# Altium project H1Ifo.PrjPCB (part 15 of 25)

## Sheet IfoSqz3A.SchDoc: D1800185
size C; Engineer: Daniel Sigg; DocumentNumber: 6; Revision: 4; SheetNumber: 6; SheetTotal: 10
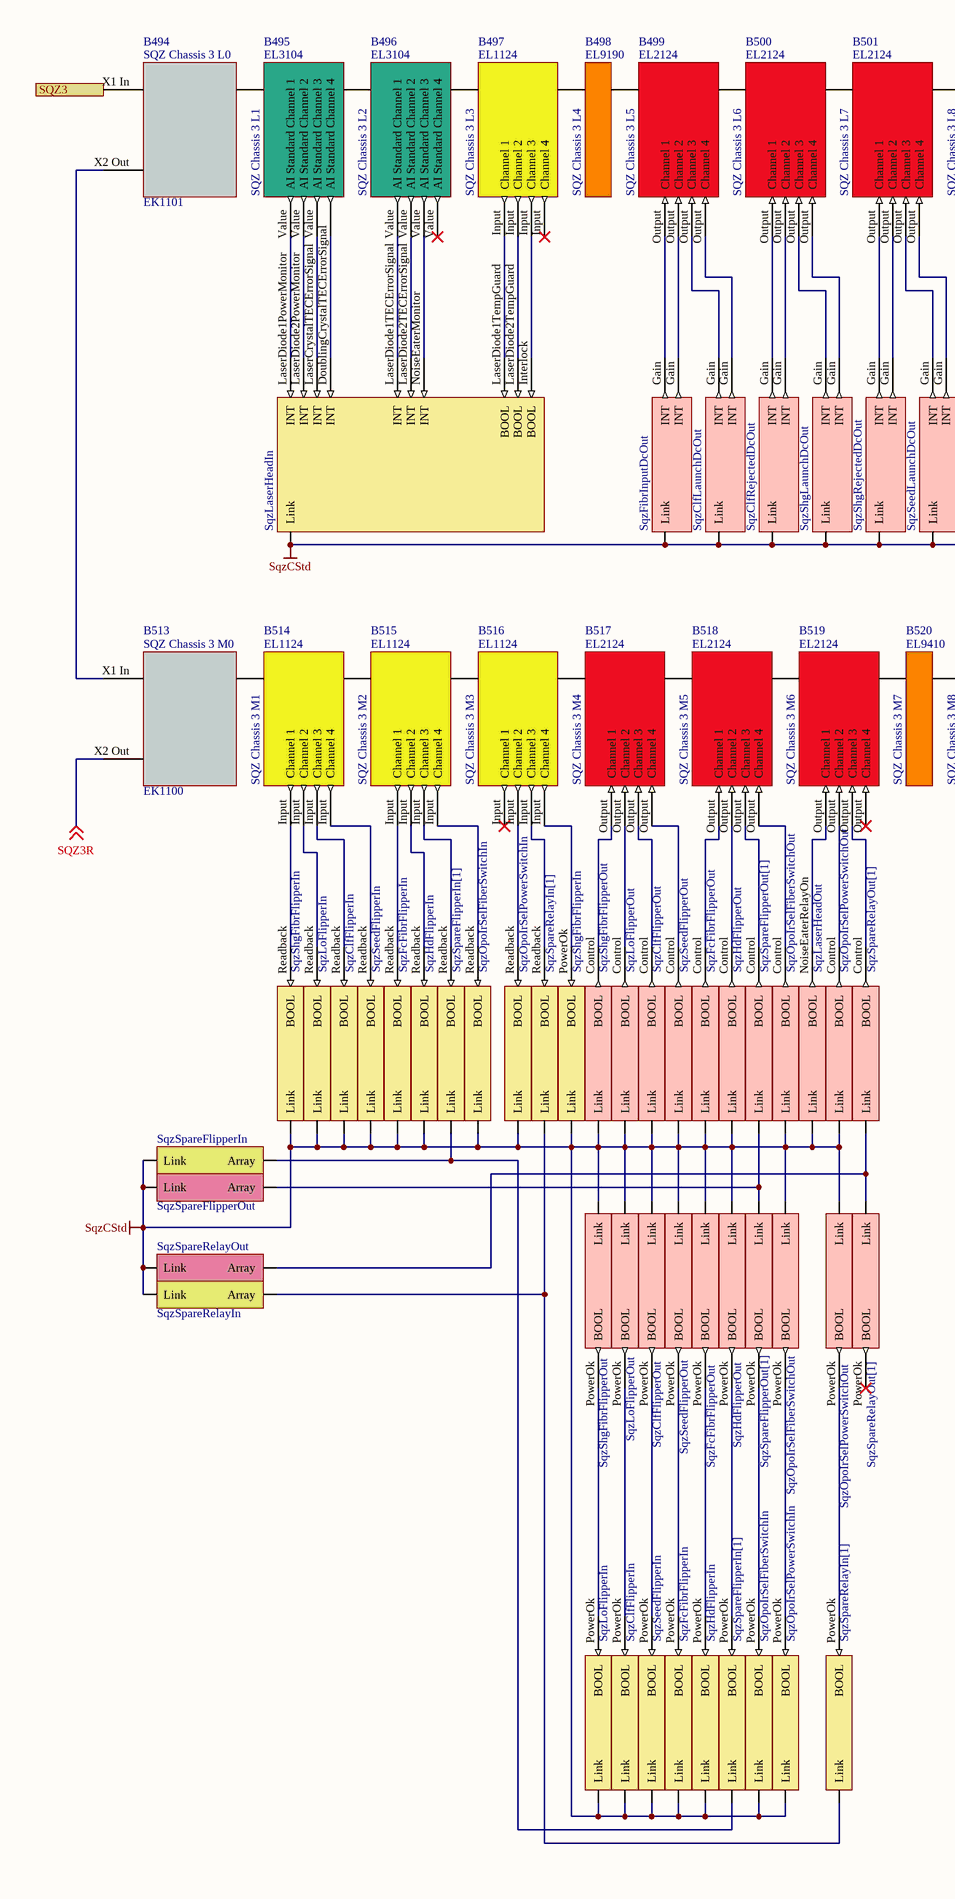
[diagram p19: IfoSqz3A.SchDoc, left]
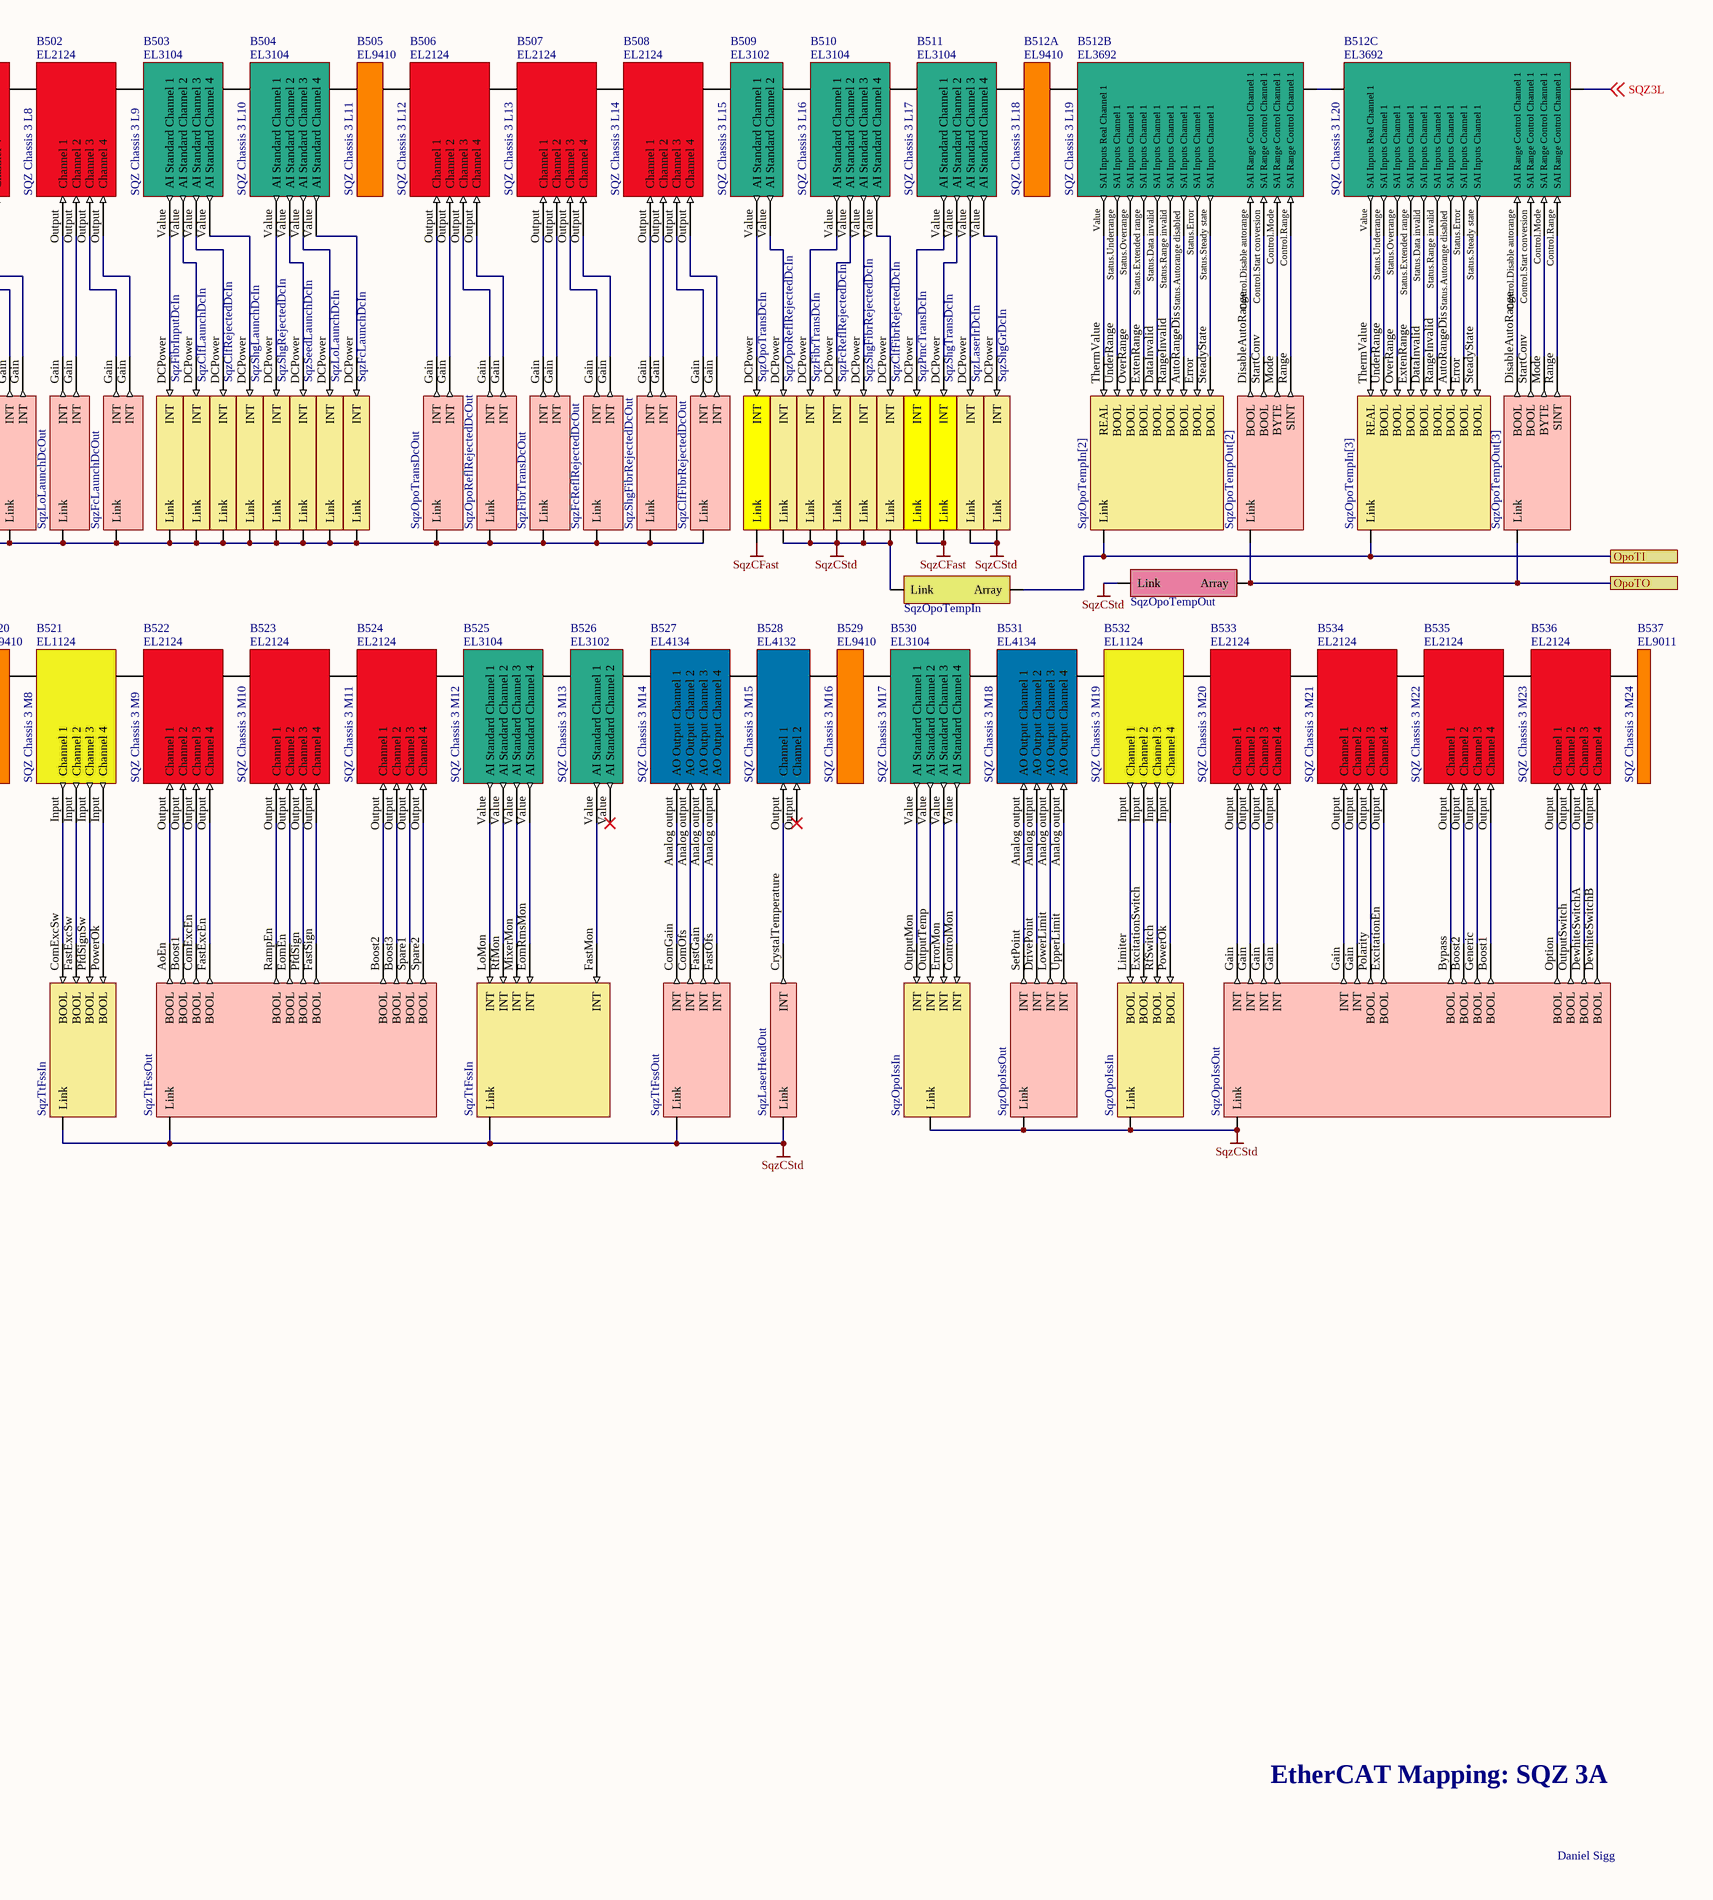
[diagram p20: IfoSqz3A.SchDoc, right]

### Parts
B494  SQZ Chassis 3 L0  Part Number: EK1101
B495  SQZ Chassis 3 L1  Part Number: EL3104  (mechanical)
B496  SQZ Chassis 3 L2  Part Number: EL3104  (mechanical)
B497  SQZ Chassis 3 L3  Part Number: EL1124  (mechanical)
B498  SQZ Chassis 3 L4  Part Number: EL9190  (mechanical)
B499  SQZ Chassis 3 L5  Part Number: EL2124  (mechanical)
B500  SQZ Chassis 3 L6  Part Number: EL2124  (mechanical)
B501  SQZ Chassis 3 L7  Part Number: EL2124  (mechanical)
B502  SQZ Chassis 3 L8  Part Number: EL2124  (mechanical)
B503  SQZ Chassis 3 L9  Part Number: EL3104  (mechanical)
B504  SQZ Chassis 3 L10  Part Number: EL3104  (mechanical)
B505  SQZ Chassis 3 L11  Part Number: EL9410  (mechanical)
B506  SQZ Chassis 3 L12  Part Number: EL2124  (mechanical)
B507  SQZ Chassis 3 L13  Part Number: EL2124  (mechanical)
B508  SQZ Chassis 3 L14  Part Number: EL2124  (mechanical)
B509  SQZ Chassis 3 L15  Part Number: EL3102  (mechanical)
B510  SQZ Chassis 3 L16  Part Number: EL3104  (mechanical)
B511  SQZ Chassis 3 L17  Part Number: EL3104  (mechanical)
B512A  SQZ Chassis 3 L18  Part Number: EL9410  (mechanical)
B512B  SQZ Chassis 3 L19  Part Number: EL3692  (mechanical)
B512C  SQZ Chassis 3 L20  Part Number: EL3692  (mechanical)
B513  SQZ Chassis 3 M0  Part Number: EK1100
B514  SQZ Chassis 3 M1  Part Number: EL1124  (mechanical)
B515  SQZ Chassis 3 M2  Part Number: EL1124  (mechanical)
B516  SQZ Chassis 3 M3  Part Number: EL1124  (mechanical)
B517  SQZ Chassis 3 M4  Part Number: EL2124  (mechanical)
B518  SQZ Chassis 3 M5  Part Number: EL2124  (mechanical)
B519  SQZ Chassis 3 M6  Part Number: EL2124  (mechanical)
B520  SQZ Chassis 3 M7  Part Number: EL9410  (mechanical)
B521  SQZ Chassis 3 M8  Part Number: EL1124  (mechanical)
B522  SQZ Chassis 3 M9  Part Number: EL2124  (mechanical)
B523  SQZ Chassis 3 M10  Part Number: EL2124  (mechanical)
B524  SQZ Chassis 3 M11  Part Number: EL2124  (mechanical)
B525  SQZ Chassis 3 M12  Part Number: EL3104  (mechanical)
B526  SQZ Chassis 3 M13  Part Number: EL3102  (mechanical)
B527  SQZ Chassis 3 M14  Part Number: EL4134  (mechanical)
B528  SQZ Chassis 3 M15  Part Number: EL4132  (mechanical)
B529  SQZ Chassis 3 M16  Part Number: EL9410  (mechanical)
B530  SQZ Chassis 3 M17  Part Number: EL3104  (mechanical)
B531  SQZ Chassis 3 M18  Part Number: EL4134  (mechanical)
B532  SQZ Chassis 3 M19  Part Number: EL1124  (mechanical)
B533  SQZ Chassis 3 M20  Part Number: EL2124  (mechanical)
B534  SQZ Chassis 3 M21  Part Number: EL2124  (mechanical)
B535  SQZ Chassis 3 M22  Part Number: EL2124  (mechanical)
B536  SQZ Chassis 3 M23  Part Number: EL2124  (mechanical)
B537  SQZ Chassis 3 M24  Part Number: EL9011  (mechanical)
V25  SqzOpoIssIn  (parts A,B of 2)  (no BOM)
V325  SqzLaserHeadOut  (parts A,B of 2)  (no BOM)
V356  SqzShgFibrFlipperIn  (parts A,B of 2)  (no BOM)
V357  SqzLoFlipperIn  (parts A,B of 2)  (no BOM)
V358  SqzClfFlipperIn  (parts A,B of 2)  (no BOM)
V359  SqzSeedFlipperIn  (parts A,B of 2)  (no BOM)
V360  SqzFcFibrFlipperIn  (parts A,B of 2)  (no BOM)
V361  SqzHdFlipperIn  (parts A,B of 2)  (no BOM)
V362  SqzSpareFlipperIn[1]  (parts A,B of 2)  (no BOM)
V363  SqzOpoIrSelFiberSwitchIn  (parts A,B of 2)  (no BOM)
V364  SqzOpoIrSelPowerSwitchIn  (parts A,B of 2)  (no BOM)
V365  SqzSpareRelayIn[1]  (parts A,B of 2)  (no BOM)
V366  SqzShgFibrFlipperOut  (parts A,B of 2)  (no BOM)
V367  SqzLoFlipperOut  (parts A,B of 2)  (no BOM)
V368  SqzClfFlipperOut  (parts A,B of 2)  (no BOM)
V369  SqzSeedFlipperOut  (parts A,B of 2)  (no BOM)
V370  SqzFcFibrFlipperOut  (parts A,B of 2)  (no BOM)
V371  SqzHdFlipperOut  (parts A,B of 2)  (no BOM)
V372  SqzSpareFlipperOut[1]  (parts A,B of 2)  (no BOM)
V373  SqzOpoIrSelFiberSwitchOut  (parts A,B of 2)  (no BOM)
V374  SqzOpoIrSelPowerSwitchOut  (parts A,B of 2)  (no BOM)
V375  SqzSpareRelayOut[1]  (parts A,B of 2)  (no BOM)
V380  SqzTtFssIn  (parts A,B of 2)  (no BOM)
V381  SqzTtFssOut  (parts A,B of 2)  (no BOM)
V437  SqzOpoIssOut  (parts A,B of 2)  (no BOM)
V459  SqzLaserHeadIn  (no BOM)
V460  SqzFibrInputDcOut  (no BOM)
V461  SqzClfLaunchDcOut  (no BOM)
V462  SqzClfRejectedDcOut  (no BOM)
V463  SqzShgLaunchDcOut  (no BOM)
V464  SqzShgRejectedDcOut  (no BOM)
V465  SqzSeedLaunchDcOut  (no BOM)
V466  SqzLoLaunchDcOut  (no BOM)
V467  SqzFcLaunchDcOut  (no BOM)
V468  SqzFibrInputDcIn  (no BOM)
V469  SqzClfLaunchDcIn  (no BOM)
V470  SqzClfRejectedDcIn  (no BOM)
V471  SqzShgLaunchDcIn  (no BOM)
V472  SqzShgRejectedDcIn  (no BOM)
V473  SqzSeedLaunchDcIn  (no BOM)
V474  SqzLoLaunchDcIn  (no BOM)
V475  SqzFcLaunchDcIn  (no BOM)
V476  SqzOpoTransDcOut  (no BOM)
V481  SqzOpoReflRejectedDcOut  (no BOM)
V482  SqzFibrTransDcOut  (no BOM)
V483  SqzFcReflRejectedDcOut  (no BOM)
V484  SqzShgFibrRejectedDcOut  (no BOM)
V485  SqzClfFibrRejectedDcOut  (no BOM)
V486  SqzOpoTransDcIn  (no BOM)
V487  SqzOpoReflRejectedDcIn  (no BOM)
V490  SqzFibrTransDcIn  (no BOM)
V491  SqzFcReflRejectedDcIn  (no BOM)
V492  SqzShgFibrRejectedDcIn  (no BOM)
V493  SqzClfFibrRejectedDcIn  (no BOM)
V495  SqzShgTransDcIn  (no BOM)
V496  SqzLaserIrDcIn  (no BOM)
V497  SqzShgGrDcIn  (no BOM)
V498  SqzOpoTempIn[2]  (no BOM)
V499  SqzOpoTempOut[2]  (no BOM)
V500  SqzOpoTempIn[3]  (no BOM)
V501  SqzOpoTempOut[3]  (no BOM)
V502  SqzOpoTempOut  (no BOM)
V503  SqzOpoTempIn  (no BOM)
V504  SqzSpareFlipperIn  (no BOM)
V505  SqzSpareFlipperOut  (no BOM)
V506  SqzSpareRelayOut  (no BOM)
V507  SqzSpareRelayIn  (no BOM)
V874  SqzPmcTransDcIn  (no BOM)

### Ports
OpoTI, OpoTO, SQZ3

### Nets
SqzCFast: V486.1(Link) V495.1(Link) V874.1(Link)
SqzCStd: V25.0(Link) V25.1(Link) V325.0(Link) V325.1(Link) V356.0(Link) V356.1(Link) V357.0(Link) V357.1(Link) V358.0(Link) V358.1(Link) V359.0(Link) V359.1(Link) V360.0(Link) V360.1(Link) V361.0(Link) V361.1(Link) V363.0(Link) V363.1(Link) V364.0(Link) V364.1(Link) V366.0(Link) V366.1(Link) V367.0(Link) V367.1(Link) V368.0(Link) V368.1(Link) V369.0(Link) V369.1(Link) V370.0(Link) V370.1(Link) V371.0(Link) V371.1(Link) V373.0(Link) V373.1(Link) V374.0(Link) V374.1(Link) V380.0(Link) V380.1(Link) V381.0(Link) V381.1(Link) V437.0(Link) V437.1(Link) V459.0(Link) V460.0(Link) V461.0(Link) V462.0(Link) V463.0(Link) V464.0(Link) V465.0(Link) V466.0(Link) V467.0(Link) V468.1(Link) V469.1(Link) V470.1(Link) V471.1(Link) V472.1(Link) V473.1(Link) V474.1(Link) V475.1(Link) V476.0(Link) V481.0(Link) V482.0(Link) V483.0(Link) V484.0(Link) V485.0(Link) V487.1(Link) V490.1(Link) V491.1(Link) V492.1(Link) V493.1(Link) V496.1(Link) V497.1(Link) V502.?1(Link) V503.?1(Link) V504.?1(Link) V505.?1(Link) V506.?1(Link) V507.?1(Link)
SQZ3L: B512C.Ebus(B) ; off-sheet SQZ3L
SQZ3R: B513.X2_Out(C) ; off-sheet SQZ3R
NetB473_X2 Out: B494.X1_In(A) ; port SQZ3
NetB494_Ebus: B494.Ebus(B) B495.Ebus(A)
NetB494_X2 Out: B494.X2_Out(C) B513.X1_In(A)
NetB495_Ebus: B495.Ebus(B) B496.Ebus(A)
NetB495_Value: B495.Value(AI_Standard_Channel_1) V459.LaserDiode1PowerMonitor(INT)
NetB495_Value: B495.Value(AI_Standard_Channel_2) V459.LaserDiode2PowerMonitor(INT)  [a separate net that carries the same name]
NetB495_Value: B495.Value(AI_Standard_Channel_3) V459.LaserCrystalTECErrorSignal(INT)  [a separate net that carries the same name]
NetB495_Value: B495.Value(AI_Standard_Channel_4) V459.DoublingCrystalTECErrorSignal(INT)  [a separate net that carries the same name]
NetB496_Ebus: B496.Ebus(B) B497.Ebus(A)
NetB496_Value: B496.Value(AI_Standard_Channel_1) V459.LaserDiode1TECErrorSignal(INT)
NetB496_Value: B496.Value(AI_Standard_Channel_2) V459.LaserDiode2TECErrorSignal(INT)  [a separate net that carries the same name]
NetB496_Value: B496.Value(AI_Standard_Channel_3) V459.NoiseEaterMonitor(INT)  [a separate net that carries the same name]
NetB497_Ebus: B497.Ebus(B) B498.Ebus(A)
NetB497_Input: B497.Input(Channel_1) V459.LaserDiode1TempGuard(BOOL)
NetB497_Input: B497.Input(Channel_2) V459.LaserDiode2TempGuard(BOOL)  [a separate net that carries the same name]
NetB497_Input: B497.Input(Channel_3) V459.Interlock(BOOL)  [a separate net that carries the same name]
NetB498_Ebus: B498.Ebus(B) B499.Ebus(A)
NetB499_Ebus: B499.Ebus(B) B500.Ebus(A)
NetB499_Output: B499.Output(Channel_1) V460.Gain(INT)
NetB499_Output: B499.Output(Channel_2) V460.Gain(INT)  [a separate net that carries the same name]
NetB499_Output: B499.Output(Channel_3) V461.Gain(INT)  [a separate net that carries the same name]
NetB499_Output: B499.Output(Channel_4) V461.Gain(INT)  [a separate net that carries the same name]
NetB500_Ebus: B500.Ebus(B) B501.Ebus(A)
NetB500_Output: B500.Output(Channel_1) V462.Gain(INT)
NetB500_Output: B500.Output(Channel_2) V462.Gain(INT)  [a separate net that carries the same name]
NetB500_Output: B500.Output(Channel_3) V463.Gain(INT)  [a separate net that carries the same name]
NetB500_Output: B500.Output(Channel_4) V463.Gain(INT)  [a separate net that carries the same name]
NetB501_Ebus: B501.Ebus(B) B502.Ebus(A)
NetB501_Output: B501.Output(Channel_1) V464.Gain(INT)
NetB501_Output: B501.Output(Channel_2) V464.Gain(INT)  [a separate net that carries the same name]
NetB501_Output: B501.Output(Channel_3) V465.Gain(INT)  [a separate net that carries the same name]
NetB501_Output: B501.Output(Channel_4) V465.Gain(INT)  [a separate net that carries the same name]
NetB502_Ebus: B502.Ebus(B) B503.Ebus(A)
NetB502_Output: B502.Output(Channel_1) V466.Gain(INT)
NetB502_Output: B502.Output(Channel_2) V466.Gain(INT)  [a separate net that carries the same name]
NetB502_Output: B502.Output(Channel_3) V467.Gain(INT)  [a separate net that carries the same name]
NetB502_Output: B502.Output(Channel_4) V467.Gain(INT)  [a separate net that carries the same name]
NetB503_Ebus: B503.Ebus(B) B504.Ebus(A)
NetB503_Value: B503.Value(AI_Standard_Channel_1) V468.DCPower(INT)
NetB503_Value: B503.Value(AI_Standard_Channel_2) V469.DCPower(INT)  [a separate net that carries the same name]
NetB503_Value: B503.Value(AI_Standard_Channel_3) V470.DCPower(INT)  [a separate net that carries the same name]
NetB503_Value: B503.Value(AI_Standard_Channel_4) V471.DCPower(INT)  [a separate net that carries the same name]
NetB504_Ebus: B504.Ebus(B) B505.Ebus(A)
NetB504_Value: B504.Value(AI_Standard_Channel_1) V472.DCPower(INT)
NetB504_Value: B504.Value(AI_Standard_Channel_2) V473.DCPower(INT)  [a separate net that carries the same name]
NetB504_Value: B504.Value(AI_Standard_Channel_3) V474.DCPower(INT)  [a separate net that carries the same name]
NetB504_Value: B504.Value(AI_Standard_Channel_4) V475.DCPower(INT)  [a separate net that carries the same name]
NetB505_Ebus: B505.Ebus(B) B506.Ebus(A)
NetB506_Ebus: B506.Ebus(B) B507.Ebus(A)
NetB506_Output: B506.Output(Channel_1) V476.Gain(INT)
NetB506_Output: B506.Output(Channel_2) V476.Gain(INT)  [a separate net that carries the same name]
NetB506_Output: B506.Output(Channel_3) V481.Gain(INT)  [a separate net that carries the same name]
NetB506_Output: B506.Output(Channel_4) V481.Gain(INT)  [a separate net that carries the same name]
NetB507_Ebus: B507.Ebus(B) B508.Ebus(A)
NetB507_Output: B507.Output(Channel_1) V482.Gain(INT)
NetB507_Output: B507.Output(Channel_2) V482.Gain(INT)  [a separate net that carries the same name]
NetB507_Output: B507.Output(Channel_3) V483.Gain(INT)  [a separate net that carries the same name]
NetB507_Output: B507.Output(Channel_4) V483.Gain(INT)  [a separate net that carries the same name]
NetB508_Ebus: B508.Ebus(B) B509.Ebus(A)
NetB508_Output: B508.Output(Channel_1) V484.Gain(INT)
NetB508_Output: B508.Output(Channel_2) V484.Gain(INT)  [a separate net that carries the same name]
NetB508_Output: B508.Output(Channel_3) V485.Gain(INT)  [a separate net that carries the same name]
NetB508_Output: B508.Output(Channel_4) V485.Gain(INT)  [a separate net that carries the same name]
NetB509_Ebus: B509.Ebus(B) B510.Ebus(A)
NetB509_Value: B509.Value(AI_Standard_Channel_1) V486.DCPower(INT)
NetB509_Value: B509.Value(AI_Standard_Channel_2) V487.DCPower(INT)  [a separate net that carries the same name]
NetB510_Ebus: B510.Ebus(B) B511.Ebus(A)
NetB510_Value: B510.Value(AI_Standard_Channel_1) V490.DCPower(INT)
NetB510_Value: B510.Value(AI_Standard_Channel_2) V491.DCPower(INT)  [a separate net that carries the same name]
NetB510_Value: B510.Value(AI_Standard_Channel_3) V492.DCPower(INT)  [a separate net that carries the same name]
NetB510_Value: B510.Value(AI_Standard_Channel_4) V493.DCPower(INT)  [a separate net that carries the same name]
NetB511_Ebus: B511.Ebus(B) B512A.Ebus(A)
NetB511_Value: B511.Value(AI_Standard_Channel_1) V874.DCPower(INT)
NetB511_Value: B511.Value(AI_Standard_Channel_2) V495.DCPower(INT)  [a separate net that carries the same name]
NetB511_Value: B511.Value(AI_Standard_Channel_3) V496.DCPower(INT)  [a separate net that carries the same name]
NetB511_Value: B511.Value(AI_Standard_Channel_4) V497.DCPower(INT)  [a separate net that carries the same name]
NetB512A_Ebus: B512A.Ebus(B) B512B.Ebus(A)
NetB512B_Control.Disable autorange: B512B.Control.Disable_autorange(SAI_Range_Control_Channel_1) V499.DisableAutoRange(BOOL)
NetB512B_Control.Mode: B512B.Control.Mode(SAI_Range_Control_Channel_1) V499.Mode(BYTE)
NetB512B_Control.Range: B512B.Control.Range(SAI_Range_Control_Channel_1) V499.Range(SINT)
NetB512B_Control.Start conversion: B512B.Control.Start_conversion(SAI_Range_Control_Channel_1) V499.StartConv(BOOL)
NetB512B_Ebus: B512B.Ebus(B) B512C.Ebus(A)
NetB512B_Status.Autorange disabled: B512B.Status.Autorange_disabled(SAI_Inputs_Channel_1) V498.AutoRangeDis(BOOL)
NetB512B_Status.Data invalid: B512B.Status.Data_invalid(SAI_Inputs_Channel_1) V498.DataInvalid(BOOL)
NetB512B_Status.Error: B512B.Status.Error(SAI_Inputs_Channel_1) V498.Error(BOOL)
NetB512B_Status.Extended range: B512B.Status.Extended_range(SAI_Inputs_Channel_1) V498.ExtenRange(BOOL)
NetB512B_Status.Overrange: B512B.Status.Overrange(SAI_Inputs_Channel_1) V498.OverRange(BOOL)
NetB512B_Status.Range invalid: B512B.Status.Range_invalid(SAI_Inputs_Channel_1) V498.RangeInvalid(BOOL)
NetB512B_Status.Steady state: B512B.Status.Steady_state(SAI_Inputs_Channel_1) V498.SteadyState(BOOL)
NetB512B_Status.Underrange: B512B.Status.Underrange(SAI_Inputs_Channel_1) V498.UnderRange(BOOL)
NetB512B_Value: B512B.Value(SAI_Inputs_Real_Channel_1) V498.ThermValue(REAL)
NetB512C_Control.Disable autorange: B512C.Control.Disable_autorange(SAI_Range_Control_Channel_1) V501.DisableAutoRange(BOOL)
NetB512C_Control.Mode: B512C.Control.Mode(SAI_Range_Control_Channel_1) V501.Mode(BYTE)
NetB512C_Control.Range: B512C.Control.Range(SAI_Range_Control_Channel_1) V501.Range(SINT)
NetB512C_Control.Start conversion: B512C.Control.Start_conversion(SAI_Range_Control_Channel_1) V501.StartConv(BOOL)
NetB512C_Status.Autorange disabled: B512C.Status.Autorange_disabled(SAI_Inputs_Channel_1) V500.AutoRangeDis(BOOL)
NetB512C_Status.Data invalid: B512C.Status.Data_invalid(SAI_Inputs_Channel_1) V500.DataInvalid(BOOL)
NetB512C_Status.Error: B512C.Status.Error(SAI_Inputs_Channel_1) V500.Error(BOOL)
NetB512C_Status.Extended range: B512C.Status.Extended_range(SAI_Inputs_Channel_1) V500.ExtenRange(BOOL)
NetB512C_Status.Overrange: B512C.Status.Overrange(SAI_Inputs_Channel_1) V500.OverRange(BOOL)
NetB512C_Status.Range invalid: B512C.Status.Range_invalid(SAI_Inputs_Channel_1) V500.RangeInvalid(BOOL)
NetB512C_Status.Steady state: B512C.Status.Steady_state(SAI_Inputs_Channel_1) V500.SteadyState(BOOL)
NetB512C_Status.Underrange: B512C.Status.Underrange(SAI_Inputs_Channel_1) V500.UnderRange(BOOL)
NetB512C_Value: B512C.Value(SAI_Inputs_Real_Channel_1) V500.ThermValue(REAL)
NetB513_Ebus: B513.Ebus(B) B514.Ebus(A)
NetB514_Ebus: B514.Ebus(B) B515.Ebus(A)
NetB514_Input: B514.Input(Channel_1) V356.Readback(BOOL)
NetB514_Input: B514.Input(Channel_2) V357.Readback(BOOL)  [a separate net that carries the same name]
NetB514_Input: B514.Input(Channel_3) V358.Readback(BOOL)  [a separate net that carries the same name]
NetB514_Input: B514.Input(Channel_4) V359.Readback(BOOL)  [a separate net that carries the same name]
NetB515_Ebus: B515.Ebus(B) B516.Ebus(A)
NetB515_Input: B515.Input(Channel_1) V360.Readback(BOOL)
NetB515_Input: B515.Input(Channel_2) V361.Readback(BOOL)  [a separate net that carries the same name]
NetB515_Input: B515.Input(Channel_3) V362.Readback(BOOL)  [a separate net that carries the same name]
NetB515_Input: B515.Input(Channel_4) V363.Readback(BOOL)  [a separate net that carries the same name]
NetB516_Ebus: B516.Ebus(B) B517.Ebus(A)
NetB516_Input: B516.Input(Channel_1) V364.Readback(BOOL)
NetB516_Input: B516.Input(Channel_3) V365.Readback(BOOL)  [a separate net that carries the same name]
NetB516_Input: B516.Input(Channel_4) V356.PowerOk(BOOL)  [a separate net that carries the same name]
NetB517_Ebus: B517.Ebus(B) B518.Ebus(A)
NetB517_Output: B517.Output(Channel_1) V366.Control(BOOL)
NetB517_Output: B517.Output(Channel_2) V367.Control(BOOL)  [a separate net that carries the same name]
NetB517_Output: B517.Output(Channel_3) V368.Control(BOOL)  [a separate net that carries the same name]
NetB517_Output: B517.Output(Channel_4) V369.Control(BOOL)  [a separate net that carries the same name]
NetB518_Ebus: B518.Ebus(B) B519.Ebus(A)
NetB518_Output: B518.Output(Channel_1) V370.Control(BOOL)
NetB518_Output: B518.Output(Channel_2) V371.Control(BOOL)  [a separate net that carries the same name]
NetB518_Output: B518.Output(Channel_3) V372.Control(BOOL)  [a separate net that carries the same name]
NetB518_Output: B518.Output(Channel_4) V373.Control(BOOL)  [a separate net that carries the same name]
NetB519_Ebus: B519.Ebus(B) B520.Ebus(A)
NetB519_Output: B519.Output(Channel_1) V325.NoiseEaterRelayOn(BOOL)
NetB519_Output: B519.Output(Channel_2) V374.Control(BOOL)  [a separate net that carries the same name]
NetB519_Output: B519.Output(Channel_3) V375.Control(BOOL)  [a separate net that carries the same name]
NetB520_Ebus: B520.Ebus(B) B521.Ebus(A)
NetB521_Ebus: B521.Ebus(B) B522.Ebus(A)
NetB521_Input: B521.Input(Channel_1) V380.ComExcSw(BOOL)
NetB521_Input: B521.Input(Channel_2) V380.FastExcSw(BOOL)  [a separate net that carries the same name]
NetB521_Input: B521.Input(Channel_3) V380.PfdSignSw(BOOL)  [a separate net that carries the same name]
NetB521_Input: B521.Input(Channel_4) V380.PowerOk(BOOL)  [a separate net that carries the same name]
NetB522_Ebus: B522.Ebus(B) B523.Ebus(A)
NetB522_Output: B522.Output(Channel_1) V381.AoEn(BOOL)
NetB522_Output: B522.Output(Channel_2) V381.Boost1(BOOL)  [a separate net that carries the same name]
NetB522_Output: B522.Output(Channel_3) V381.ComExcEn(BOOL)  [a separate net that carries the same name]
NetB522_Output: B522.Output(Channel_4) V381.FastExcEn(BOOL)  [a separate net that carries the same name]
NetB523_Ebus: B523.Ebus(B) B524.Ebus(A)
NetB523_Output: B523.Output(Channel_1) V381.RampEn(BOOL)
NetB523_Output: B523.Output(Channel_2) V381.EomEn(BOOL)  [a separate net that carries the same name]
NetB523_Output: B523.Output(Channel_3) V381.PfdSign(BOOL)  [a separate net that carries the same name]
NetB523_Output: B523.Output(Channel_4) V381.FastSign(BOOL)  [a separate net that carries the same name]
NetB524_Ebus: B524.Ebus(B) B525.Ebus(A)
NetB524_Output: B524.Output(Channel_1) V381.Boost2(BOOL)
NetB524_Output: B524.Output(Channel_2) V381.Boost3(BOOL)  [a separate net that carries the same name]
NetB524_Output: B524.Output(Channel_3) V381.Spare1(BOOL)  [a separate net that carries the same name]
NetB524_Output: B524.Output(Channel_4) V381.Spare2(BOOL)  [a separate net that carries the same name]
NetB525_Ebus: B525.Ebus(B) B526.Ebus(A)
NetB525_Value: B525.Value(AI_Standard_Channel_1) V380.LoMon(INT)
NetB525_Value: B525.Value(AI_Standard_Channel_2) V380.RfMon(INT)  [a separate net that carries the same name]
NetB525_Value: B525.Value(AI_Standard_Channel_3) V380.MixerMon(INT)  [a separate net that carries the same name]
NetB525_Value: B525.Value(AI_Standard_Channel_4) V380.EomRmsMon(INT)  [a separate net that carries the same name]
NetB526_Ebus: B526.Ebus(B) B527.Ebus(A)
NetB526_Value: B526.Value(AI_Standard_Channel_1) V380.FastMon(INT)
NetB527_Analog output: B527.Analog_output(AO_Output_Channel_1) V381.ComGain(INT)
NetB527_Analog output: B527.Analog_output(AO_Output_Channel_2) V381.ComOfs(INT)  [a separate net that carries the same name]
NetB527_Analog output: B527.Analog_output(AO_Output_Channel_3) V381.FastGain(INT)  [a separate net that carries the same name]
NetB527_Analog output: B527.Analog_output(AO_Output_Channel_4) V381.FastOfs(INT)  [a separate net that carries the same name]
NetB527_Ebus: B527.Ebus(B) B528.Ebus(A)
NetB528_Ebus: B528.Ebus(B) B529.Ebus(A)
NetB528_Output: B528.Output(Channel_1) V325.CrystalTemperature(INT)
NetB529_Ebus: B529.Ebus(B) B530.Ebus(A)
NetB530_Ebus: B530.Ebus(B) B531.Ebus(A)
NetB530_Value: B530.Value(AI_Standard_Channel_1) V25.OutputMon(INT)
NetB530_Value: B530.Value(AI_Standard_Channel_2) V25.OutputTemp(INT)  [a separate net that carries the same name]
NetB530_Value: B530.Value(AI_Standard_Channel_3) V25.ErrorMon(INT)  [a separate net that carries the same name]
NetB530_Value: B530.Value(AI_Standard_Channel_4) V25.ControlMon(INT)  [a separate net that carries the same name]
NetB531_Analog output: B531.Analog_output(AO_Output_Channel_1) V437.SetPoint(INT)
NetB531_Analog output: B531.Analog_output(AO_Output_Channel_2) V437.DrivePoint(INT)  [a separate net that carries the same name]
NetB531_Analog output: B531.Analog_output(AO_Output_Channel_3) V437.LowerLimit(INT)  [a separate net that carries the same name]
NetB531_Analog output: B531.Analog_output(AO_Output_Channel_4) V437.UpperLimit(INT)  [a separate net that carries the same name]
NetB531_Ebus: B531.Ebus(B) B532.Ebus(A)
NetB532_Ebus: B532.Ebus(B) B533.Ebus(A)
NetB532_Input: B532.Input(Channel_1) V25.Limiter(BOOL)
NetB532_Input: B532.Input(Channel_2) V25.ExcitationSwitch(BOOL)  [a separate net that carries the same name]
NetB532_Input: B532.Input(Channel_3) V25.RfSwitch(BOOL)  [a separate net that carries the same name]
NetB532_Input: B532.Input(Channel_4) V25.PowerOk(BOOL)  [a separate net that carries the same name]
NetB533_Ebus: B533.Ebus(B) B534.Ebus(A)
NetB533_Output: B533.Output(Channel_1) V437.Gain(INT)
NetB533_Output: B533.Output(Channel_2) V437.Gain(INT)  [a separate net that carries the same name]
NetB533_Output: B533.Output(Channel_3) V437.Gain(INT)  [a separate net that carries the same name]
NetB533_Output: B533.Output(Channel_4) V437.Gain(INT)  [a separate net that carries the same name]
NetB534_Ebus: B534.Ebus(B) B535.Ebus(A)
NetB534_Output: B534.Output(Channel_1) V437.Gain(INT)
NetB534_Output: B534.Output(Channel_2) V437.Gain(INT)  [a separate net that carries the same name]
NetB534_Output: B534.Output(Channel_3) V437.Polarity(BOOL)  [a separate net that carries the same name]
NetB534_Output: B534.Output(Channel_4) V437.ExcitationEn(BOOL)  [a separate net that carries the same name]
NetB535_Ebus: B535.Ebus(B) B536.Ebus(A)
NetB535_Output: B535.Output(Channel_1) V437.Bypass(BOOL)
NetB535_Output: B535.Output(Channel_2) V437.Boost2(BOOL)  [a separate net that carries the same name]
NetB535_Output: B535.Output(Channel_3) V437.Generic(BOOL)  [a separate net that carries the same name]
NetB535_Output: B535.Output(Channel_4) V437.Boost1(BOOL)  [a separate net that carries the same name]
NetB536_Ebus: B536.Ebus(B) B537.Ebus(A)
NetB536_Output: B536.Output(Channel_1) V437.Option(BOOL)
NetB536_Output: B536.Output(Channel_2) V437.OutputSwitch(BOOL)  [a separate net that carries the same name]
NetB536_Output: B536.Output(Channel_3) V437.DewhiteSwitchA(BOOL)  [a separate net that carries the same name]
NetB536_Output: B536.Output(Channel_4) V437.DewhiteSwitchB(BOOL)  [a separate net that carries the same name]
NetV357_PowerOk: V357.PowerOk(BOOL) V366.PowerOk(BOOL)
NetV358_PowerOk: V358.PowerOk(BOOL) V367.PowerOk(BOOL)
NetV359_PowerOk: V359.PowerOk(BOOL) V368.PowerOk(BOOL)
NetV360_PowerOk: V360.PowerOk(BOOL) V369.PowerOk(BOOL)
NetV361_PowerOk: V361.PowerOk(BOOL) V370.PowerOk(BOOL)
NetV362_0: V362.0(Link) V362.1(Link) V504.?2(Array)
NetV362_PowerOk: V362.PowerOk(BOOL) V371.PowerOk(BOOL)
NetV363_PowerOk: V363.PowerOk(BOOL) V372.PowerOk(BOOL)
NetV364_PowerOk: V364.PowerOk(BOOL) V373.PowerOk(BOOL)
NetV365_0: V365.0(Link) V365.1(Link) V507.?2(Array)
NetV365_PowerOk: V365.PowerOk(BOOL) V374.PowerOk(BOOL)
NetV372_0: V372.0(Link) V372.1(Link) V505.?2(Array)
NetV375_0: V375.0(Link) V375.1(Link) V506.?2(Array)
NetV453_1: V498.1(Link) V500.1(Link) V503.?2(Array) ; port OpoTI
NetV454_1: V499.1(Link) V501.1(Link) V502.?2(Array) ; port OpoTO

Not connected (* = marked no-connect by the designer): V375 PowerOk(BOOL)*

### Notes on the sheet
- EtherCAT Mapping: SQZ 3A
- Daniel Sigg

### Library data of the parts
B494 = CouplerEK1101: EtherCAT Coupler; Rail: Left; BoxNextB: AJKJLVSL; BoxNextC: VQWTFMVH; BoxPrev: TJPFHJJD; PortPrevFull: 1102/C; PortPrevShort: C 'X2 Out'; Fullname: TIID^Vertex Squeezer (EtherCAT)^SQZ Chassis 3 L0 (EK1101); BoxPorts: Junction; BoxAddr: 1122; Disabled: False
B495 = TerminalEL3104: EtherCAT Terminal EL3104 4-chn Analog Input; Rail: Left; BoxNextB: IHJTPWGR; BoxPrev: FMRHTNIC; PortPrevFull: 1122/B; PortPrevShort: B; Fullname: TIID^Vertex Squeezer (EtherCAT)^SQZ Chassis 3 L0 (EK1101)^SQZ Chassis 3 L1 (EL3104); BoxAddr: 1123; Disabled: False
B496 = TerminalEL3104: EtherCAT Terminal EL3104 4-chn Analog Input; Rail: Left; BoxNextB: FQMKKJFJ; BoxPrev: AJKJLVSL; PortPrevFull: 1123/B; PortPrevShort: B; Fullname: TIID^Vertex Squeezer (EtherCAT)^SQZ Chassis 3 L0 (EK1101)^SQZ Chassis 3 L2 (EL3104); BoxAddr: 1124; Disabled: False
B497 = TerminalEL1124: EtherCAT Terminal EL1124 4-chn Digital Input; Rail: Left; BoxNextB: EDMFAODK; BoxPrev: IHJTPWGR; PortPrevFull: 1124/B; PortPrevShort: B; Fullname: TIID^Vertex Squeezer (EtherCAT)^SQZ Chassis 3 L0 (EK1101)^SQZ Chassis 3 L3 (EL1124); BoxAddr: 1125; Disabled: False
B498 = TerminalEL9190: EtherCAT Terminal EL9190 Supply; BoxType: TerminalPassive; Rail: Left; BoxNextB: ATHKEAWU; BoxPrev: FQMKKJFJ; PortPrevShort: B; Fullname: TIID^Vertex Squeezer (EtherCAT)^SQZ Chassis 3 L0 (EK1101)^SQZ Chassis 3 L4 (EL9190); Disabled: False
B499 = TerminalEL2124: EtherCAT Terminal EL2124 4-chn Digital Ouput; Rail: Left; BoxNextB: WIRAEIOD; BoxPrev: EDMFAODK; PortPrevFull: 1125/B; PortPrevShort: B; Fullname: TIID^Vertex Squeezer (EtherCAT)^SQZ Chassis 3 L0 (EK1101)^SQZ Chassis 3 L5 (EL2124); BoxAddr: 1126; Disabled: False
B500 = TerminalEL2124: EtherCAT Terminal EL2124 4-chn Digital Ouput; Rail: Left; BoxNextB: NSIBAFKB; BoxPrev: ATHKEAWU; PortPrevFull: 1126/B; PortPrevShort: B; Fullname: TIID^Vertex Squeezer (EtherCAT)^SQZ Chassis 3 L0 (EK1101)^SQZ Chassis 3 L6 (EL2124); BoxAddr: 1127; Disabled: False
B501 = TerminalEL2124: EtherCAT Terminal EL2124 4-chn Digital Ouput; Rail: Left; BoxNextB: QSDJXBJL; BoxPrev: WIRAEIOD; PortPrevFull: 1127/B; PortPrevShort: B; Fullname: TIID^Vertex Squeezer (EtherCAT)^SQZ Chassis 3 L0 (EK1101)^SQZ Chassis 3 L7 (EL2124); BoxAddr: 1128; Disabled: False
B502 = TerminalEL2124: EtherCAT Terminal EL2124 4-chn Digital Ouput; Rail: Left; BoxNextB: STPSOKFX; BoxPrev: NSIBAFKB; PortPrevFull: 1128/B; PortPrevShort: B; Fullname: TIID^Vertex Squeezer (EtherCAT)^SQZ Chassis 3 L0 (EK1101)^SQZ Chassis 3 L8 (EL2124); BoxAddr: 1129; Disabled: False
B503 = TerminalEL3104: EtherCAT Terminal EL3104 4-chn Analog Input; Rail: Left; BoxNextB: RMBRTWXS; BoxPrev: QSDJXBJL; PortPrevFull: 1129/B; PortPrevShort: B; Fullname: TIID^Vertex Squeezer (EtherCAT)^SQZ Chassis 3 L0 (EK1101)^SQZ Chassis 3 L9 (EL3104); BoxAddr: 1130; Disabled: False
B504 = TerminalEL3104: EtherCAT Terminal EL3104 4-chn Analog Input; Rail: Left; BoxNextB: NARRFEUQ; BoxPrev: STPSOKFX; PortPrevFull: 1130/B; PortPrevShort: B; Fullname: TIID^Vertex Squeezer (EtherCAT)^SQZ Chassis 3 L0 (EK1101)^SQZ Chassis 3 L10 (EL3104); BoxAddr: 1131; Disabled: False
B505 = TerminalEL9410: EtherCAT Terminal EL9410 Power; Rail: Left; BoxNextB: FYHJDVKP; BoxPrev: RMBRTWXS; PortPrevFull: 1131/B; PortPrevShort: B; Fullname: TIID^Vertex Squeezer (EtherCAT)^SQZ Chassis 3 L0 (EK1101)^SQZ Chassis 3 L11 (EL9410); BoxAddr: 1132; Disabled: False
B506 = TerminalEL2124: EtherCAT Terminal EL2124 4-chn Digital Ouput; Rail: Left; BoxNextB: GONMIXJR; BoxPrev: NARRFEUQ; PortPrevFull: 1132/B; PortPrevShort: B; Fullname: TIID^Vertex Squeezer (EtherCAT)^SQZ Chassis 3 L0 (EK1101)^SQZ Chassis 3 L12 (EL2124); BoxAddr: 1133; Disabled: False
B507 = TerminalEL2124: EtherCAT Terminal EL2124 4-chn Digital Ouput; Rail: Left; BoxNextB: QDSIJMPO; BoxPrev: FYHJDVKP; PortPrevFull: 1133/B; PortPrevShort: B; Fullname: TIID^Vertex Squeezer (EtherCAT)^SQZ Chassis 3 L0 (EK1101)^SQZ Chassis 3 L13 (EL2124); BoxAddr: 1134; Disabled: False
B508 = TerminalEL2124: EtherCAT Terminal EL2124 4-chn Digital Ouput; Rail: Left; BoxNextB: MVXHPUYE; BoxPrev: GONMIXJR; PortPrevFull: 1134/B; PortPrevShort: B; Fullname: TIID^Vertex Squeezer (EtherCAT)^SQZ Chassis 3 L0 (EK1101)^SQZ Chassis 3 L14 (EL2124); BoxAddr: 1135; Disabled: False
B509 = TerminalEL3102: EtherCAT Terminal EL3102 2-chn Analog Input; Rail: Left; BoxNextB: XWLKAHIG; BoxPrev: QDSIJMPO; PortPrevFull: 1135/B; PortPrevShort: B; Fullname: TIID^Vertex Squeezer (EtherCAT)^SQZ Chassis 3 L0 (EK1101)^SQZ Chassis 3 L15 (EL3102); BoxAddr: 1136; Disabled: False
B510 = TerminalEL3104: EtherCAT Terminal EL3104 4-chn Analog Input; Rail: Left; BoxNextB: IVIIOXWS; BoxPrev: MVXHPUYE; PortPrevFull: 1136/B; PortPrevShort: B; Fullname: TIID^Vertex Squeezer (EtherCAT)^SQZ Chassis 3 L0 (EK1101)^SQZ Chassis 3 L16 (EL3104); BoxAddr: 1137; Disabled: False
B511 = TerminalEL3104: EtherCAT Terminal EL3104 4-chn Analog Input; Rail: Left; BoxNextB: GUQNXUAE; BoxPrev: XWLKAHIG; PortPrevFull: 1137/B; PortPrevShort: B; Fullname: TIID^Vertex Squeezer (EtherCAT)^SQZ Chassis 3 L0 (EK1101)^SQZ Chassis 3 L17 (EL3104); BoxAddr: 1138; Disabled: False
B512A = TerminalEL9410: EtherCAT Terminal EL9410 Power; Rail: Left; BoxNextB: VSOCEONT; BoxPrev: IVIIOXWS; PortPrevFull: 1138/B; PortPrevShort: B; Fullname: TIID^Vertex Squeezer (EtherCAT)^SQZ Chassis 3 L0 (EK1101)^SQZ Chassis 3 L18 (EL9410); BoxAddr: 1139; Disabled: False
B512B = TerminalEL3692-1chn: EtherCAT Terminal EL3692 1-chn Resistance Measurement; Rail: Left; BoxNextB: FHTRRYRM; BoxPrev: GUQNXUAE; PortPrevFull: 1139/B; PortPrevShort: B; Fullname: TIID^Vertex Squeezer (EtherCAT)^SQZ Chassis 3 L0 (EK1101)^SQZ Chassis 3 L19 (EL3692); BoxAddr: 1140; PDO Inputs: 0x1A00,0x1A02; PDO Outputs: 0x1600; Disabled: False
B512C = TerminalEL3692-1chn: EtherCAT Terminal EL3692 1-chn Resistance Measurement; Rail: Left; BoxNextB: BXXLOSJW; BoxPrev: VSOCEONT; PortPrevFull: 1140/B; PortPrevShort: B; Fullname: TIID^Vertex Squeezer (EtherCAT)^SQZ Chassis 3 L0 (EK1101)^SQZ Chassis 3 L20 (EL3692); BoxAddr: 1141; PDO Inputs: 0x1A00,0x1A02; PDO Outputs: 0x1600; Disabled: False
B513 = CouplerEK1100: EtherCAT Coupler; Rail: Middle; BoxNextB: XLSFDMKN; BoxNextC: BKUDMEPV; BoxPrev: FMRHTNIC; PortPrevFull: 1122/C; PortPrevShort: C 'X2 Out'; Fullname: TIID^Vertex Squeezer (EtherCAT)^SQZ Chassis 3 M0 (EK1100); BoxPorts: Junction; BoxAddr: 1144; Disabled: False
B514 = TerminalEL1124: EtherCAT Terminal EL1124 4-chn Digital Input; Rail: Middle; BoxNextB: TNUSVYAJ; BoxPrev: VQWTFMVH; PortPrevFull: 1144/B; PortPrevShort: B; Fullname: TIID^Vertex Squeezer (EtherCAT)^SQZ Chassis 3 M0 (EK1100)^SQZ Chassis 3 M1 (EL1124); BoxAddr: 1145; Disabled: False
B515 = TerminalEL1124: EtherCAT Terminal EL1124 4-chn Digital Input; Rail: Middle; BoxNextB: CVLMLOMA; BoxPrev: XLSFDMKN; PortPrevFull: 1145/B; PortPrevShort: B; Fullname: TIID^Vertex Squeezer (EtherCAT)^SQZ Chassis 3 M0 (EK1100)^SQZ Chassis 3 M2 (EL1124); BoxAddr: 1146; Disabled: False
B516 = TerminalEL1124: EtherCAT Terminal EL1124 4-chn Digital Input; Rail: Middle; BoxNextB: IRBONRTN; BoxPrev: TNUSVYAJ; PortPrevFull: 1146/B; PortPrevShort: B; Fullname: TIID^Vertex Squeezer (EtherCAT)^SQZ Chassis 3 M0 (EK1100)^SQZ Chassis 3 M3 (EL1124); BoxAddr: 1147; Disabled: False
B517 = TerminalEL2124: EtherCAT Terminal EL2124 4-chn Digital Ouput; Rail: Middle; BoxNextB: THEVFFGL; BoxPrev: CVLMLOMA; PortPrevFull: 1147/B; PortPrevShort: B; Fullname: TIID^Vertex Squeezer (EtherCAT)^SQZ Chassis 3 M0 (EK1100)^SQZ Chassis 3 M4 (EL2124); BoxAddr: 1148; Disabled: False
B518 = TerminalEL2124: EtherCAT Terminal EL2124 4-chn Digital Ouput; Rail: Middle; BoxNextB: CKQUWICU; BoxPrev: IRBONRTN; PortPrevFull: 1148/B; PortPrevShort: B; Fullname: TIID^Vertex Squeezer (EtherCAT)^SQZ Chassis 3 M0 (EK1100)^SQZ Chassis 3 M5 (EL2124); BoxAddr: 1149; Disabled: False
B519 = TerminalEL2124: EtherCAT Terminal EL2124 4-chn Digital Ouput; Rail: Middle; BoxNextB: HAUJDNYY; BoxPrev: THEVFFGL; PortPrevFull: 1149/B; PortPrevShort: B; Fullname: TIID^Vertex Squeezer (EtherCAT)^SQZ Chassis 3 M0 (EK1100)^SQZ Chassis 3 M6 (EL2124); BoxAddr: 1150; Disabled: False
B520 = TerminalEL9410: EtherCAT Terminal EL9410 Power; Rail: Middle; BoxNextB: SMLVNEDU; BoxPrev: CKQUWICU; PortPrevFull: 1150/B; PortPrevShort: B; Fullname: TIID^Vertex Squeezer (EtherCAT)^SQZ Chassis 3 M0 (EK1100)^SQZ Chassis 3 M7 (EL9410); BoxAddr: 1151; Disabled: False
B521 = TerminalEL1124: EtherCAT Terminal EL1124 4-chn Digital Input; Rail: Middle; BoxNextB: IDJDJWQI; BoxPrev: HAUJDNYY; PortPrevFull: 1151/B; PortPrevShort: B; Fullname: TIID^Vertex Squeezer (EtherCAT)^SQZ Chassis 3 M0 (EK1100)^SQZ Chassis 3 M8 (EL1124); BoxAddr: 1152; Disabled: False
B522 = TerminalEL2124: EtherCAT Terminal EL2124 4-chn Digital Ouput; Rail: Middle; BoxNextB: GXMHCXGM; BoxPrev: SMLVNEDU; PortPrevFull: 1152/B; PortPrevShort: B; Fullname: TIID^Vertex Squeezer (EtherCAT)^SQZ Chassis 3 M0 (EK1100)^SQZ Chassis 3 M9 (EL2124); BoxAddr: 1153; Disabled: False
B523 = TerminalEL2124: EtherCAT Terminal EL2124 4-chn Digital Ouput; Rail: Middle; BoxNextB: GSOEKFDP; BoxPrev: IDJDJWQI; PortPrevFull: 1153/B; PortPrevShort: B; Fullname: TIID^Vertex Squeezer (EtherCAT)^SQZ Chassis 3 M0 (EK1100)^SQZ Chassis 3 M10 (EL2124); BoxAddr: 1154; Disabled: False
B524 = TerminalEL2124: EtherCAT Terminal EL2124 4-chn Digital Ouput; Rail: Middle; BoxNextB: DRXWXPDE; BoxPrev: GXMHCXGM; PortPrevFull: 1154/B; PortPrevShort: B; Fullname: TIID^Vertex Squeezer (EtherCAT)^SQZ Chassis 3 M0 (EK1100)^SQZ Chassis 3 M11 (EL2124); BoxAddr: 1155; Disabled: False
B525 = TerminalEL3104: EtherCAT Terminal EL3104 4-chn Analog Input; Rail: Middle; BoxNextB: QDOAPXUR; BoxPrev: GSOEKFDP; PortPrevFull: 1155/B; PortPrevShort: B; Fullname: TIID^Vertex Squeezer (EtherCAT)^SQZ Chassis 3 M0 (EK1100)^SQZ Chassis 3 M12 (EL3104); BoxAddr: 1156; Disabled: False
B526 = TerminalEL3102: EtherCAT Terminal EL3102 2-chn Analog Input; Rail: Middle; BoxNextB: NTCWHDAS; BoxPrev: DRXWXPDE; PortPrevFull: 1156/B; PortPrevShort: B; Fullname: TIID^Vertex Squeezer (EtherCAT)^SQZ Chassis 3 M0 (EK1100)^SQZ Chassis 3 M13 (EL3102); BoxAddr: 1157; Disabled: False
B527 = TerminalEL4134: EtherCAT Terminal EL4134 4-chn Analog Ouput; Rail: Middle; BoxNextB: UKFKIXUT; BoxPrev: QDOAPXUR; PortPrevFull: 1157/B; PortPrevShort: B; Fullname: TIID^Vertex Squeezer (EtherCAT)^SQZ Chassis 3 M0 (EK1100)^SQZ Chassis 3 M14 (EL4134); BoxAddr: 1158; Disabled: False
B528 = TerminalEL4132: EtherCAT Terminal EL4132 2-chn Analog Ouput; Rail: Middle; BoxNextB: XHNPMAXV; BoxPrev: NTCWHDAS; PortPrevFull: 1158/B; PortPrevShort: B; Fullname: TIID^Vertex Squeezer (EtherCAT)^SQZ Chassis 3 M0 (EK1100)^SQZ Chassis 3 M15 (EL4132); BoxAddr: 1159; Disabled: False
B529 = TerminalEL9410: EtherCAT Terminal EL9410 Power; Rail: Middle; BoxNextB: QEUIUGBY; BoxPrev: UKFKIXUT; PortPrevFull: 1159/B; PortPrevShort: B; Fullname: TIID^Vertex Squeezer (EtherCAT)^SQZ Chassis 3 M0 (EK1100)^SQZ Chassis 3 M16 (EL9410); BoxAddr: 1160; Disabled: False
B530 = TerminalEL3104: EtherCAT Terminal EL3104 4-chn Analog Input; Rail: Middle; BoxNextB: HYNRMALA; BoxPrev: XHNPMAXV; PortPrevFull: 1160/B; PortPrevShort: B; Fullname: TIID^Vertex Squeezer (EtherCAT)^SQZ Chassis 3 M0 (EK1100)^SQZ Chassis 3 M17 (EL3104); BoxAddr: 1161; Disabled: False
B531 = TerminalEL4134: EtherCAT Terminal EL4134 4-chn Analog Ouput; Rail: Middle; BoxNextB: DVRKLIGT; BoxPrev: QEUIUGBY; PortPrevFull: 1161/B; PortPrevShort: B; Fullname: TIID^Vertex Squeezer (EtherCAT)^SQZ Chassis 3 M0 (EK1100)^SQZ Chassis 3 M18 (EL4134); BoxAddr: 1162; Disabled: False
B532 = TerminalEL1124: EtherCAT Terminal EL1124 4-chn Digital Input; Rail: Middle; BoxNextB: YEKHTTYV; BoxPrev: HYNRMALA; PortPrevFull: 1162/B; PortPrevShort: B; Fullname: TIID^Vertex Squeezer (EtherCAT)^SQZ Chassis 3 M0 (EK1100)^SQZ Chassis 3 M19 (EL1124); BoxAddr: 1163; Disabled: False
B533 = TerminalEL2124: EtherCAT Terminal EL2124 4-chn Digital Ouput; Rail: Middle; BoxNextB: MWFMKUPP; BoxPrev: DVRKLIGT; PortPrevFull: 1163/B; PortPrevShort: B; Fullname: TIID^Vertex Squeezer (EtherCAT)^SQZ Chassis 3 M0 (EK1100)^SQZ Chassis 3 M20 (EL2124); BoxAddr: 1164; Disabled: False
B534 = TerminalEL2124: EtherCAT Terminal EL2124 4-chn Digital Ouput; Rail: Middle; BoxNextB: YKZGOKQO; BoxPrev: YEKHTTYV; PortPrevFull: 1164/B; PortPrevShort: B; Fullname: TIID^Vertex Squeezer (EtherCAT)^SQZ Chassis 3 M0 (EK1100)^SQZ Chassis 3 M21 (EL2124); BoxAddr: 1165; Disabled: False
B535 = TerminalEL2124: EtherCAT Terminal EL2124 4-chn Digital Ouput; Rail: Middle; BoxNextB: AYJAKQAY; BoxPrev: MWFMKUPP; PortPrevFull: 1165/B; PortPrevShort: B; Fullname: TIID^Vertex Squeezer (EtherCAT)^SQZ Chassis 3 M0 (EK1100)^SQZ Chassis 3 M22 (EL2124); BoxAddr: 1166; Disabled: False
B536 = TerminalEL2124: EtherCAT Terminal EL2124 4-chn Digital Ouput; Rail: Middle; BoxNextB: VMMNVUID; BoxPrev: YKZGOKQO; PortPrevFull: 1166/B; PortPrevShort: B; Fullname: TIID^Vertex Squeezer (EtherCAT)^SQZ Chassis 3 M0 (EK1100)^SQZ Chassis 3 M23 (EL2124); BoxAddr: 1167; Disabled: False
B537 = TerminalEL9011: EtherCAT Terminal EL9011 End; BoxType: TerminalPassive; Rail: Middle; BoxPrev: AYJAKQAY; PortPrevShort: B; Fullname: TIID^Vertex Squeezer (EtherCAT)^SQZ Chassis 3 M0 (EK1100)^SQZ Chassis 3 M24 (EL9011); Disabled: False
V25 = Iss_AomServoInStruct: AomServoInStruct; BoxType: Variable; Instance: H1SqzCorner Instance; PLC: H1SqzCorner; Task: SqzCStd
V325 = ALSLaser_ALSLaserOutStructB: ALSLaserOutStruct; BoxType: Variable; Instance: H1SqzCorner Instance; PLC: H1SqzCorner; Task: SqzCStd
V356-V365 = MotorizedFlipper_MotorizedFlipperInStruct: MotorizedFlipperInStruct; BoxType: Variable; Instance: H1SqzCorner Instance; PLC: H1SqzCorner; Task: SqzCStd
V366-V375 = MotorizedFlipper_MotorizedFlipperOutStruct: MotorizedFlipperOutStruct; BoxType: Variable; Instance: H1SqzCorner Instance; PLC: H1SqzCorner; Task: SqzCStd
V380 = TtFssV4_TtFssV4InStruct: TtFssV4InStruct; BoxType: Variable; Instance: H1SqzCorner Instance; PLC: H1SqzCorner; Task: SqzCStd
V381 = TtFssV4_TtFssV4OutStruct: TtFssV4OutStruct; BoxType: Variable; Instance: H1SqzCorner Instance; PLC: H1SqzCorner; Task: SqzCStd
V437 = Iss_AomServoOutStruct: AomServoOutStruct; BoxType: Variable; Instance: H1SqzCorner Instance; PLC: H1SqzCorner; Task: SqzCStd
V459 = ALSLaser_ALSLaserInStruct: ALSLaserInStruct; BoxType: Variable; Instance: H1SqzCorner Instance; PLC: H1SqzCorner; Task: SqzCStd
V460-V467 V476 V481-V485 = DCPower_DCPowerOutStruct: DCPowerOutStruct; BoxType: Variable; Instance: H1SqzCorner Instance; PLC: H1SqzCorner; Task: SqzCStd
V468-V475 V487 V490-V493 V496 V497 = DCPower_DCPowerInStruct: DCPowerInStruct; BoxType: Variable; Instance: H1SqzCorner Instance; PLC: H1SqzCorner; Task: SqzCStd
V486 V495 V874 = DCPower_DCPowerFastInStruct: DCPowerInStruct; BoxType: Variable; Instance: H1SqzCorner Instance; PLC: H1SqzCorner; Task: SqzCFast
V498 V500 = TECController_ThermistorInStruct: ThermistorInStruct; BoxType: Variable; Instance: H1SqzCorner Instance; PLC: H1SqzCorner; Task: SqzCStd
V499 V501 = TECController_ThermistorOutStruct: ThermistorOutStruct; BoxType: Variable; Instance: H1SqzCorner Instance; PLC: H1SqzCorner; Task: SqzCStd
V502 = ArrayAggregatorOut: Array [1..3] Of ThermistorOutStruct; Instance: H1SqzCorner Instance; PLC: H1SqzCorner; Task: SqzCStd; Lower Bound: 1; Upper Bound: 3
V503 = ArrayAggregatorIn: Array [1..3] Of ThermistorInStruct; Instance: H1SqzCorner Instance; PLC: H1SqzCorner; Task: SqzCStd; Lower Bound: 1; Upper Bound: 3
V504 V507 = ArrayAggregatorIn: Array [1..1] Of MotorizedFlipperInStruct; Instance: H1SqzCorner Instance; PLC: H1SqzCorner; Task: SqzCStd; Lower Bound: 1
V505 V506 = ArrayAggregatorOut: Array [1..1] Of MotorizedFlipperOutStruct; Instance: H1SqzCorner Instance; PLC: H1SqzCorner; Task: SqzCStd; Lower Bound: 1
